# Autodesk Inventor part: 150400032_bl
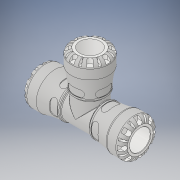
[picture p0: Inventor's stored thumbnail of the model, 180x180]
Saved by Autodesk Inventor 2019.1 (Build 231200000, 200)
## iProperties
Created: 2016-12
Part Number: 150400032_bl
Material: Generic
Description: PLASSON G-PLASS TEE 32X32X32
Document SubType Name: Modeling
Designer: KIM
Mass: 664.223 g
Surface Area: 733.008 cm^2
Volume: 474.445 cm^3
Density: 1 g/cm^3
Appearance: Default
Author: KIM
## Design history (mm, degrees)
derived "150400.ipt"
feature "Solid1::150400.ipt" dims "ScaleForDerivedMember" = 10
tag "TaggingFeature1"
body "Solid1"
other parameters: "d1" = 23.52 [user parameter], "d2" = 32 [user parameter], "d4" = 58 [user parameter], "d8" = 49.3 [user parameter], "d13" = 7.2 [user parameter], "d14" = 7.2 [user parameter], "d15" = 0 [user parameter], "d17" = 360 deg [user parameter], "d19" = 8 deg [user parameter], "d20" = 0.64 [user parameter], "d21" = 0.64 [user parameter], "d22" = 8 deg [user parameter], "d24" = 0 [user parameter], "d26" = 360 deg [user parameter], "d33" = 5.8 [user parameter], "d43" = 45.24 [user parameter], "d51" = 0.58 [user parameter], "d54" = 11.2 [user parameter], "d55" = 7.04 [user parameter], "d57" = 14.112 [user parameter], "d58" = 0 [user parameter], "d74" = 0 [user parameter], "d77" = 2.66667 [user parameter], "d78" = 56 [user parameter], "d79" = 45.24 [user parameter], "d80" = 156 [user parameter], "d82" = 0.64 [user parameter], "d115" = 360 deg [user parameter], "d139" = 7.2 [user parameter], "d140" = 0 [user parameter], "d142" = 360 deg [user parameter], "d207" = 90 deg [user parameter], "d209" = 23.52 [user parameter], "d210" = 32 [user parameter], "d212" = 58 [user parameter], "d213" = 49.3 [user parameter], "d215" = 45.24 [user parameter], "d216" = 2.66667 [user parameter], "d217" = 56 [user parameter], "d225" = 86 [user parameter], "d226" = 56 [user parameter], "d228" = 9.52 [user parameter], "d229" = 7.2 [user parameter], "d233" = 7.2 [user parameter], "d234" = 0 [user parameter], "d236" = 360 deg [user parameter], "d238" = 8 deg [user parameter], "d239" = 8 deg [user parameter], "d240" = 0.64 [user parameter], "d241" = 0.64 [user parameter], "d243" = 0 [user parameter], "d245" = 360 deg [user parameter], "d247" = 1.16 [user parameter], "d248" = 3.36 [user parameter], "d249" = 3.36 [user parameter], "d250" = 9.52 [user parameter], "d252" = 11.2 [user parameter], "d253" = 7.36 [user parameter], "d254" = 14.112 [user parameter], "d255" = 0 [user parameter], "d257" = 360 deg [user parameter], "d259" = 0.64 [user parameter], "d261" = 0 [user parameter], "d262" = 1.16 [user parameter], "d264" = 0 [user parameter], "d266" = 0 [user parameter], "d267" = 0.58 [user parameter], "d_" = 32 [user parameter], "E_" = 58 [user parameter], "l_" = 56 [user parameter], "A_" = 86 [user parameter], "H_" = 156 [user parameter], "d9" = 9 [user parameter], "d11" = 58 [user parameter], "d230" = 58 [user parameter], "d232" = 9 [user parameter]
